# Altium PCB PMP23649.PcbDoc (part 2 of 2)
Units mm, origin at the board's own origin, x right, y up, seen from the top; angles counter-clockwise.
Board outline 75 x 70 mm, 2 copper layers (Top Layer, Bottom Layer), stack 1.575 mm thick; 49 components, 23 nets, 125 pads, 45 vias.
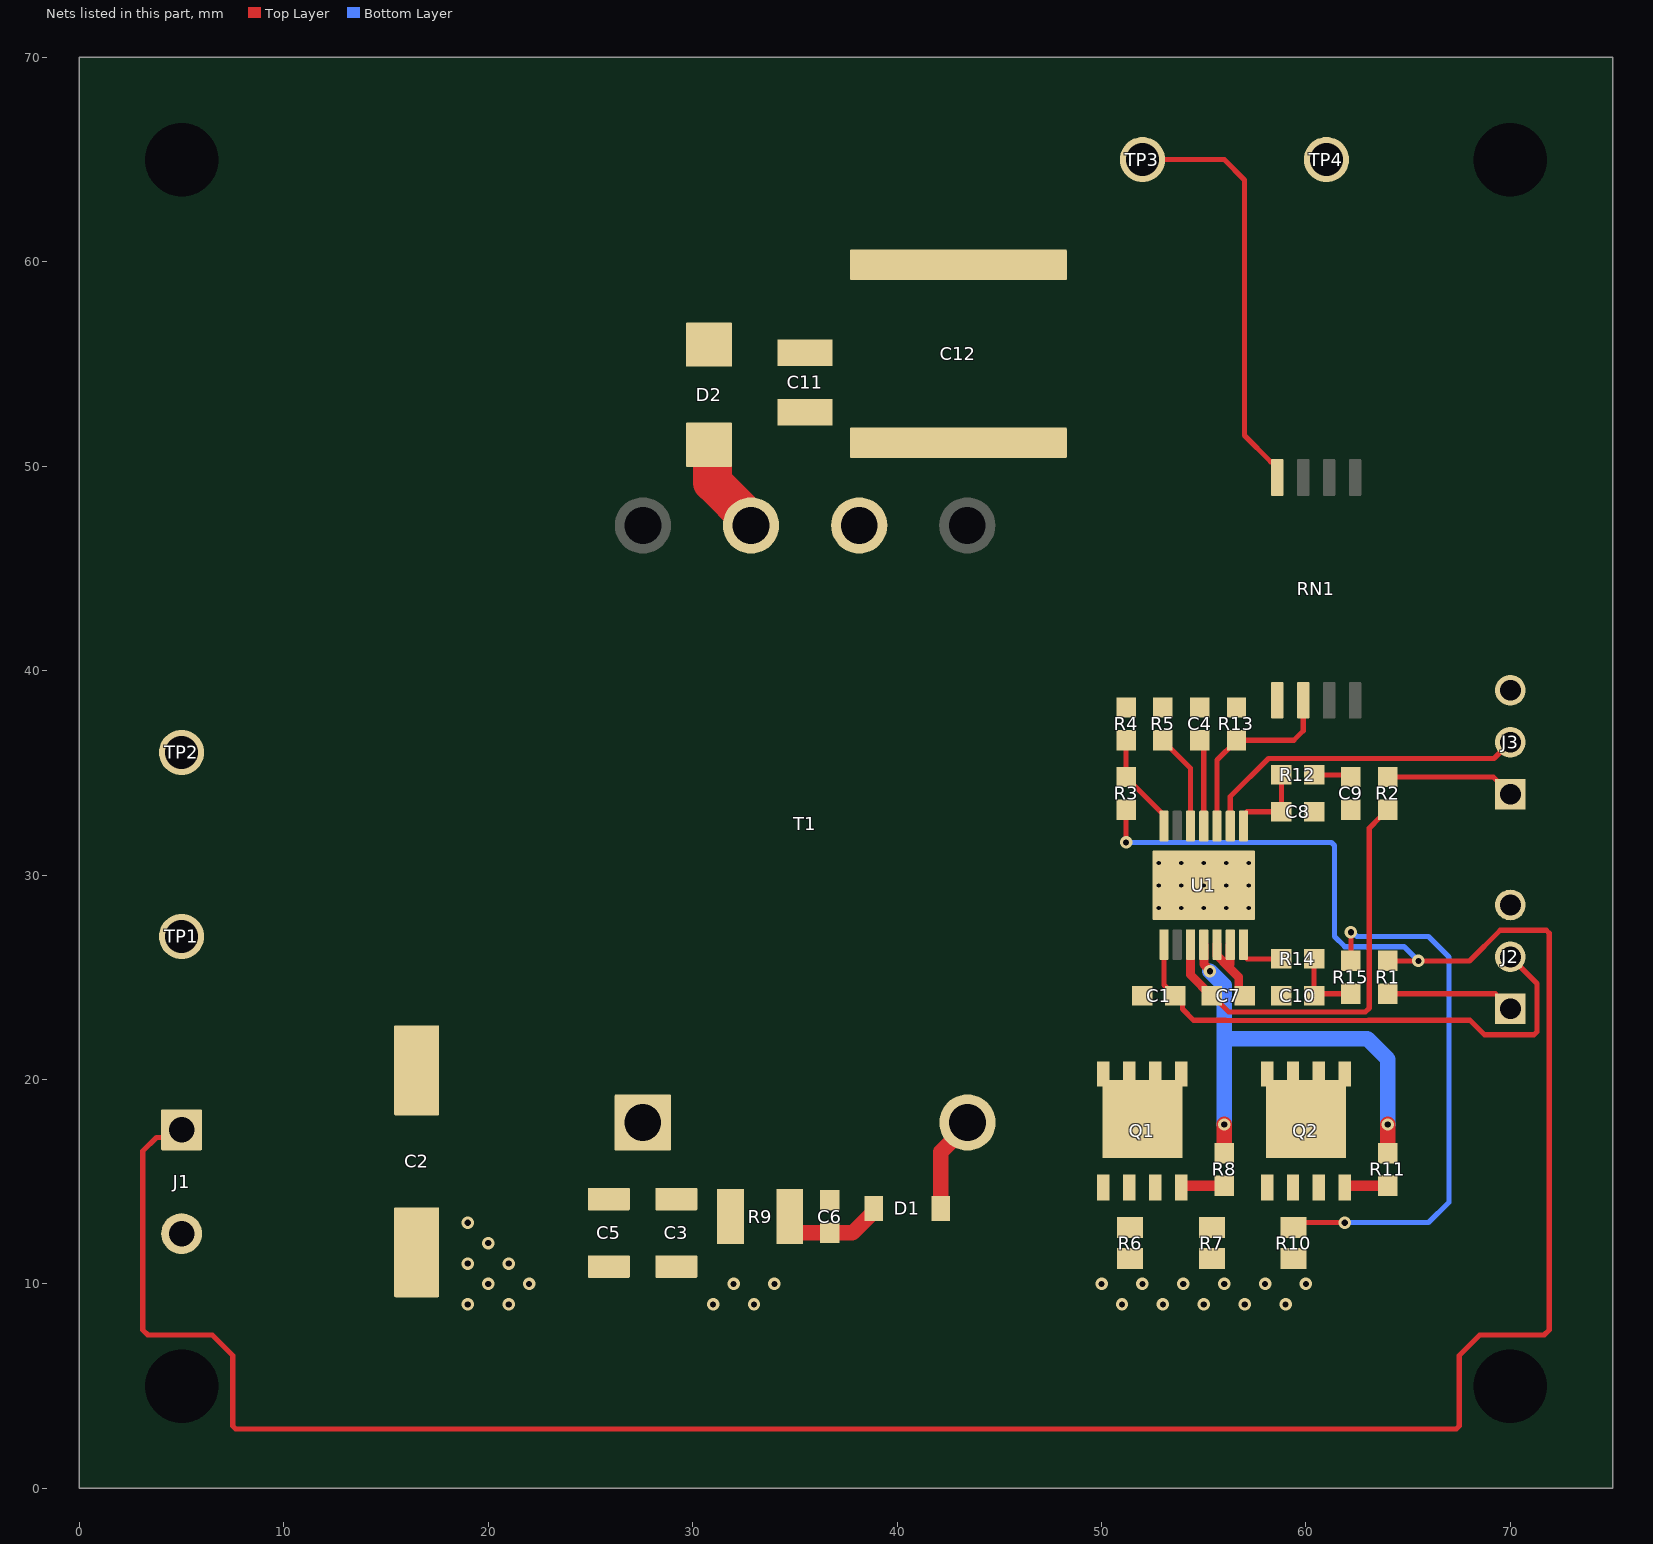
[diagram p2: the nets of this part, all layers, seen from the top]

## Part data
C1: library part CMP-0007469-4, "CAP, CERM, 0.1 uF, 100 V, +/- 10%, X7R, 0603", Cap_Case=0603, Manufacturer=MuRata, Supplier Part Number 1=490-3285-1-ND, TempCo=X7R, Tolerance_%=10%, Value1=Unknown, Value2=100V, ValueDisplayed=0.1uF
C2: library part CMP-0122594-1, "100 µF 63 V Aluminum - Polymer Capacitors Radial, Can - SMD 30mOhm 10000 Hrs @ 105°C", Digikey Part Number=565-HHXD630ARA101MJA0GCT-ND, Leakage Current=63uA, Manufacturer=Chemi-Con, Mouser Part Number=661-HHXD630ARA101MJA, Operating Temperature Range="-55°C to +105°C", Tolerance_%=20%, ValueDisplayed=100uF
C3 C5: library part CMP-0087970-1, "10µF ±10% 100V Ceramic Capacitor X7S 1210 (3225 Metric)", Manufacturer=Murata, TempCo=22%, Tolerance_%=10%, ValueDisplayed=10uF
C4 C7: library part CMP-0007338-5, "CAP, CERM, 2.2 uF, 16 V, +/- 10%, X5R, 0603", Cap_Case=0603, Manufacturer=MuRata, TempCo=X5R, Tolerance_%=10%, Value1=Unknown, Value2=16V, ValueDisplayed=2.2uF
C6: library part CMP-0007481-5, "CAP, CERM, 3900 pF, 100 V, +/- 10%, X7R, 0603", Cap_Case=0603, Manufacturer=MuRata, Supplier Part Number 1=GRM188R72A392KA01D-ND, TempCo=X7R, Tolerance_%=10%, Value1=Unknown, Value2=100V, ValueDisplayed=3900pF
C8: library part CMP-0007442-5, "CAP, CERM, 220 pF, 50 V, +/- 10%, X7R, 0603", Cap_Case=0603, Manufacturer=MuRata, Supplier Part Number 1=490-1483-1-ND, TempCo=X7R, Tolerance_%=10%, Value1=Unknown, Value2=50V, ValueDisplayed=220pF
C9: library part CMP-0007444-5, "CAP, CERM, 0.022 uF, 50 V, +/- 10%, X7R, 0603", Cap_Case=0603, Manufacturer=MuRata, Supplier Part Number 1=490-1517-1-ND, TempCo=X7R, Tolerance_%=10%, Value1=Unknown, Value2=50V, ValueDisplayed=0.022uF
C10: library part CMP-0007208-4, "CAP, CERM, 33 pF, 50 V, +/- 5%, C0G/NP0, 0603", Cap_Case=0603, Manufacturer=MuRata, Supplier Part Number 1=490-1415-1-ND, TempCo=C0G/NP0, Tolerance_%=5%, Value1=Unknown, Value2=50V, ValueDisplayed=33pF
C11: library part CMP-0009087-1, "CAP, CERM, 4700 pF, 2000 V, +/- 10%, X7R, 1210", Cap_Case=1210, Manufacturer=Kemet, TempCo=X7R, Tolerance_%=10%, Value1=Unknown, Value2=2000V, ValueDisplayed=4700pF
C12: library part CMP-0124311-1, "0.06 µF ±10% 2000V (2kV) Ceramic Capacitor C0G, NP0 3640 (9110 Metric)", Digikey Part Number=399-CKC33C603KGGLCAUTOTR-ND, Manufacturer=KEMET, Operating Temperature Range="-55°C to +150°C", TempCo=30ppm/°C, Temperature Characteristic=C0G, Tolerance_%=10%, ValueDisplayed=0.06uF
D1: library part CMP-0076920-3, "Diode, Switching, 100 V, 0.15 A, SOD-123FL", Manufacturer=Vishay-Semiconductor, Value1=0.15A, Value2=1.2V
D2: library part CMP-0124313-1, "Rectifier Diode Schottky SiC 3.3KV 0.3A 2-Pin SMB", Digikey Part Number=1242-1172-1-ND, Forward Current=0.3A, Manufacturer="GeneSiC Semiconductor", Max Surge Forward Current=2A, Mouser Part Number=905-GAP3SLT33-214, Operating Temperature Range="-55°C to +175°C", Peak Reverse Current=1uA, ValueDisplayed=93pF
H1 H2 H3 H4: library part CMP-0003652-1, Manufacturer=Keystone, Supplier Part Number 1=36-4820-ND
J1: library part CMP-0074910-1, "Terminal Block, 5.08 mm, 2x1, Brass, TH", Color=Blue, Current_A=15A, Manufacturer="On-Shore Technology", Supplier Part Number 1=ED1609-ND, Voltage_V=300V
J2 J3: library part CMP-0002338-1, "Header, 100mil, 3x1, Tin, TH", Color=Black, Current_A=3A, Manufacturer="Sullins Connector Solutions", Supplier Part Number 1=S1012E-03-ND, Voltage_V=1.8kV
Logo1: library part CMP-0074837-1, "IEC 61010-1 Hot Surface Warning"
Logo2: library part CMP-0074835-1, "IEC 61010-1 High Voltage Warning"
Logo3: library part CMP-0074847-1, "FCC_disclaimer"
Logo4: library part CMP-0074769-1
Q1 Q2: library part CMP-0084047-1, "MOSFET, N-CH, 250 V, 18.4 A, PowerPAK SO-8", Alternate Manufacturer=None, Manufacturer=Vishay-Semiconductor, Value1="? ohm", Value2="32 nC"
R1 R2: library part CMP-0025703-4, "RES, 10, 5%, 0.1 W, AEC-Q200 Grade 0, 0603", Manufacturer=Vishay-Dale, Power_W=100mW, Supplier Part Number 1=541-10GCT-ND, TempCo="200 ppm/C", Tolerance_%=5%, Value2=0.1W, Value_Code=10R0, ValueDisplayed=10
R3: library part CMP-0021990-4, "RES, 100 k, 1%, 0.1 W, AEC-Q200 Grade 0, 0603", Manufacturer=Vishay-Dale, Power_W=100mW, Supplier Part Number 1=541-100KHCT-ND, TempCo="100 ppm/C", Tolerance_%=1%, Value2=0.1W, Value_Code=100k
R4: library part CMP-0022131-4, "RES, 1.69 k, 1%, 0.1 W, AEC-Q200 Grade 0, 0603", Manufacturer=Vishay-Dale, Power_W=100mW, Supplier Part Number 1=541-1.69KHCT-ND, TempCo="100 ppm/C", Tolerance_%=1%, Value2=0.1W, Value_Code=1k69, ValueDisplayed=1.69k
R5: library part CMP-0022597-4, "RES, 78.7 k, 1%, 0.1 W, AEC-Q200 Grade 0, 0603", Manufacturer=Vishay-Dale, Power_W=100mW, Supplier Part Number 1=541-78.7KHCT-ND, TempCo="100 ppm/C", Tolerance_%=1%, Value2=0.1W, Value_Code=78k7, ValueDisplayed=78.7k
R6 R7 R10: library part CMP-0021987-2, "RES, 0.03, 1%, 0.5 W, 0805", Manufacturer=Vishay-Dale, Power_W=500mW, Supplier Part Number 1=WSLPB-.03CT-ND, TempCo="75 ppm/C", Tolerance_%=1%, Value2=0.5W, Value_Code=R030, ValueDisplayed=0.03
R8 R11: library part CMP-0025697-4, "RES, 0, 5%, 0.1 W, AEC-Q200 Grade 0, 0603", Manufacturer=Vishay-Dale, Power_W=100mW, Supplier Part Number 1=541-0.0GCT-ND, TempCo="200 ppm/C", Tolerance_%=5%, Value2=0.1W, Value_Code=0000, ValueDisplayed=0
R9: library part CMP-0083442-1, "RES, 10 k, 5%, 0.5 W, 1210", Manufacturer=Yageo, Power_W=500mW, TempCo="100 ppm/C", Tolerance_%=5%, Value2=0.5W, Value_Code=10k0, ValueDisplayed=10k
R12: library part CMP-0022066-4, "RES, 15.0 k, 1%, 0.1 W, AEC-Q200 Grade 0, 0603", Manufacturer=Vishay-Dale, Power_W=100mW, Supplier Part Number 1=541-15.0KHCT-ND, TempCo="100 ppm/C", Tolerance_%=1%, Value2=0.1W, Value_Code=15k0, ValueDisplayed=15.0k
R13: library part CMP-0022254-4, "RES, 27.4 k, 1%, 0.1 W, AEC-Q200 Grade 0, 0603", Manufacturer=Vishay-Dale, Power_W=100mW, Supplier Part Number 1=541-27.4KHCT-ND, TempCo="100 ppm/C", Tolerance_%=1%, Value2=0.1W, Value_Code=27k4, ValueDisplayed=27.4k
R14: library part CMP-0021991-4, "RES, 100, 1%, 0.1 W, AEC-Q200 Grade 0, 0603", Manufacturer=Vishay-Dale, Power_W=100mW, Supplier Part Number 1=541-100HCT-ND, TempCo="100 ppm/C", Tolerance_%=1%, Value2=0.1W, Value_Code=100R, ValueDisplayed=100
R15: library part CMP-0022109-5, "RES, 1.00 k, 1%, 0.1 W, AEC-Q200 Grade 0, 0603", Manufacturer=Vishay-Dale, Power_W=100mW, Supplier Part Number 1=541-1.00KHCT-ND, TempCo="100 ppm/C", Tolerance_%=1%, Value2=0.1W, Value_Code=1k00, ValueDisplayed=1.00k
RN1: library part CMP-0122658-1, "Automotive, 1700-V, Precision Resistive Divider", Manufacturer="Texas Instruments", Number Of Resistors=2, Operating Temperature Range="-55°C to +150°C", TempCo=1ppm/°C, Tolerance_%=0.05%
T1: library part CMP-0124541-1, "Flyback Transformer", Manufacturer=Coilcraft, Operating Temperature Range=to, Voltage_Isolation_Vrms=3.5kV
TP1 TP3: library part CMP-0055147-2, "Test Point, Multipurpose, Red, TH", Color=Red, Manufacturer="Keystone Electronics", Supplier Part Number 1=36-5010-ND
TP2 TP4: library part CMP-0055148-2, "Test Point, Multipurpose, Black, TH", Color=Black, Manufacturer="Keystone Electronics", Supplier Part Number 1=36-5011-ND
U1: library part CMP-0090862-1, "2.2-MHz Wide VIN 65-V Non-synchronous Boost/SEPIC/Flyback Controller with 150°C Junction Temperature", Manufacturer="Texas Instruments", Max Supply Voltage=60V, Min Supply Voltage=2.97V, Nominal Supply Current=490uA, Operating Temperature Range="-40°C to +150°C", Switching Frequency=100-2200kHz

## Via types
v1: diameter 0.61, hole 0.305, Top Layer to Bottom Layer, 30 vias
v2: diameter 0.5, hole 0.2, Top Layer to Bottom Layer, 15 vias

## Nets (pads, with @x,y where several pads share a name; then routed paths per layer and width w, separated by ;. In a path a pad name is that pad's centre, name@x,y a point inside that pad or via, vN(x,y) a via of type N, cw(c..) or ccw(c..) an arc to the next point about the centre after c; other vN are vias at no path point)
GND: C1.2 C2.1 C3.1 C4.2 C5.1 C7.2 C8.2 C9.2 C10.1 C11.2 C12.1 J1.2 J2.3 J3.3 R4.1 R5.1 R6.1 R7.1 R10.1 R13.1 RN1.5 T1.5 TP2.1 TP4.1 U1.5 U1.6 U1.15 | length 4.2
  Top Layer w0.432: U1.5@55.65,26.6 55.65,26.075 56.183,25.542 ; U1.6@56.3,26.6 56.291,26.591 56.291,25.65 56.183,25.542 ; C7.2@57,24.1 56.975,24.1 56.716,24.359 56.716,25.009 56.183,25.542
  other v1: 19,9 21,9 31,9 33,9 51,9 53,9 55,9 57,9 59,9 20,10 22,10 32,10 34,10 50,10 52,10 54,10 56,10 58,10 60,10 19,11 21,11 20,12 19,13
  other v2: 52.8,28.4 53.9,28.4 55,28.4 56.1,28.4 57.2,28.4 52.8,29.5 53.9,29.5 55,29.5 56.1,29.5 57.2,29.5 52.8,30.6 53.9,30.6 55,30.6 56.1,30.6 57.2,30.6
HV: C11.1 C12.2 D2.1 RN1.4 TP3.1 | length 20.7
  Top Layer w0.254: TP3.1@52,65 56,65 57,64 57,51.5 58.277,50.223 58.422,50.223 58.595,50.05 RN1.4@58.595,49.45
NetC1_1: C1.1 J2.2 U1.1 | length 25.7
  Top Layer w0.254: U1.1@53.05,26.6 53.05,24.625 53.575,24.1 53.607,24.1 53.955,23.752 53.955,23.45 54.505,22.9 56.05,22.9 56.059,22.892 63.066,22.892 63.075,22.9 68.02,22.9 68.73,22.19 71.151,22.19 71.3,22.339 71.3,24.7 J2.2@70,26
NetC2_2: C2.2 C3.2 C5.2 C6.1 J1.1 R1.1 R3.2 R9.2 T1.1 TP1.1 | length 136.9
  Top Layer w0.254: J1.1@5,17.54 4.628,17.168 3.768,17.168 3.1,16.5 3.1,7.749 3.349,7.5 6.5,7.5 7.5,6.5 7.5,3.049 7.649,2.9 67.351,2.9 67.5,3.049 67.5,6.5 68.5,7.5 71.651,7.5 71.9,7.749 71.9,27.151 71.751,27.3 69.5,27.3 68,25.8 R1.1@64,25.8 ; v1(51.2,31.6) R3.2@51.2,33.3
  Bottom Layer w0.254: v1(51.2,31.6) 61.251,31.6 61.4,31.451 61.4,27 61.9,26.5 64.8,26.5 v1(65.5,25.8)
NetC4_1: C4.1 U1.11 | length 4.3
  Top Layer w0.254: C4.1@54.8,36.6 55,36.4 U1.11@55,32.4
NetC6_2: C6.2 D1.1 R9.1 | length 4.4
  Top Layer w0.762: R9.1@35,12.4 35,12.481 35.019,12.5 C6.2@36.7,12.5 ; C6.2@36.8,12.5 37.815,12.5 38.863,13.547 D1.1@38.863,13.7
NetC7_1: C7.1 R2.2 U1.3 | length 21.2
  Top Layer w0.254: C7.1@55.4,24.1 55.425,24.1 56.227,23.298 62.898,23.298 63.1,23.5 63.1,32.3 63.627,32.827 63.652,32.827 64,33.175 R2.2@64,33.2
  Top Layer w0.432: U1.3@54.35,26.6 54.35,25.125 55.375,24.1 C7.1@55.4,24.1
NetC8_1: C8.1 R12.2 U1.8 | length 4.2
  Top Layer w0.254: U1.8@56.95,32.4 56.95,32.925 57.125,33.1 C8.1@58.8,33.1 R12.2@58.8,34.9
NetC9_1: C9.1 R12.1 | length 1.8
  Top Layer w0.254: R12.1@60.4,34.9 62.1,34.9 C9.1@62.2,34.8
NetC10_2: C10.2 R14.2 R15.2 | length 3.6
  Top Layer w0.254: R14.2@60.4,25.9 C10.2@60.4,24.1 60.5,24.2 R15.2@62.2,24.2
NetD1_2: D1.2 Q1.5 Q1.6 Q1.7 Q1.8 Q1.9 Q2.5 Q2.6 Q2.7 Q2.8 Q2.9 T1.3 | length 4.7
  Top Layer w0.762: D1.2@42.138,13.7 42.138,16.455 43.44,17.757 T1.3@43.44,17.895
NetD2_2: D2.2 T1.6 | length 4.8
  Top Layer w1.905: D2.2@30.8,51.05 30.85,51.05 30.977,50.922 30.977,49.211 32.855,47.334 T1.6@32.855,47.105
NetJ2_1: J2.1 R1.2 | length 6.3
  Top Layer w0.254: R1.2@64,24.2 69.26,24.2 J2.1@70,23.46
NetJ3_1: J3.1 R2.1 | length 6.3
  Top Layer w0.254: R2.1@64,34.8 69.16,34.8 J3.1@70,33.96
NetJ3_2: J3.2 U1.9 | length 16.2
  Top Layer w0.254: U1.9@56.3,32.4 56.3,33.837 58.165,35.702 63.681,35.702 63.683,35.7 69.2,35.7 J3.2@70,36.5
NetQ1_1: Q1.1 Q1.2 Q1.3 Q2.1 Q2.2 Q2.3 R6.2 R7.2 R10.2 R15.1 | length 26.6
  Top Layer w0.254: R10.2@59.6,12.8 59.8,13 v1(61.9,13) ; R15.1@62.2,25.8 v1(62.2,27.2)
  Bottom Layer w0.254: v1(61.9,13) 66,13 67,14 67,26 66,27 62.496,27 62.296,27.2 v1(62.2,27.2)
NetQ1_4: Q1.4 R8.1 | length 2.2
  Top Layer w0.508: Q1.4@53.9,14.7 53.9,14.744 53.956,14.8 R8.1@56,14.8
NetQ2_4: Q2.4 R11.1 | length 2
  Top Layer w0.508: Q2.4@62,14.8 R11.1@64,14.8
NetR3_1: R3.1 R4.2 U1.14 | length 5
  Top Layer w0.254: R4.2@51.2,36.6 R3.1@51.2,34.8 51.548,34.452 51.548,34.427 53.05,32.925 U1.14@53.05,32.4
NetR5_2: R5.2 U1.12 | length 4.8
  Top Layer w0.254: R5.2@53,36.6 53,36.575 54.35,35.225 U1.12@54.35,32.4
NetR8_2: R8.2 R11.2 U1.4 | length 23.6
  Top Layer w0.432: U1.4@55,26.6 55.009,26.591 55.009,25.639 55.3,25.348 v1(55.3,25.3)
  Top Layer w0.762: R8.2@56,16.4 v1(56,17.8) ; R11.2@64,16.4 v1(64,17.8)
  Bottom Layer w0.762: v1(55.3,25.3) 56,24.6 56,22 ; v1(56,17.8) 56,22 ; v1(64,17.8) 64,21 63,22 56,22
NetR13_2: R13.2 RN1.6 U1.10 | length 9.5
  Top Layer w0.254: U1.10@55.65,32.4 55.65,35.625 56.6,36.575 R13.2@56.6,36.6 59.4,36.6 59.865,37.065 RN1.6@59.865,38.55
NetR14_1: R14.1 U1.7 | length 2.4
  Top Layer w0.254: U1.7@56.95,26.6 56.95,26.075 57.125,25.9 R14.1@58.8,25.9
pads on no net: H1.0 H1.MH H2.0 H2.MH H3.0 H3.MH H4.0 H4.MH RN1.1 RN1.2 RN1.3 RN1.7 RN1.8 T1.4 T1.7 U1.2 U1.13

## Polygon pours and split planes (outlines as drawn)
GND on Top Layer "TOP_LAYER_GND_P004" (solid, remove dead copper, pour order 4): 34,53.5 34,51.8 34.2,51.8 36.5,49.5 36.5,46 37,45.5 39.5,45.5 40,46 40,47.8 41.2,49 47,49 48.5,47.5 48.5,15.8 3.1,15.8 3,15.7 3,2.4 72,2.4 72,41 57,41 55,43 55,48.5 51.5,52 38.5,52 37,53.5
NetC2_2 on Top Layer "TOP_LAYER_NETC2_2_P003" (solid, remove dead copper, pour order 3): 3,16 3,30 22.5,30 22.5,22.5 25,20 38,20 38,12 23,12 19,16
NetQ1_1 on Top Layer "TOP_LAYER_NETQ1_1_P002" (solid, remove dead copper, pour order 2): 49.6,16 49.6,12.3 61.1,12.3 61.1,16
NetD1_2 on Top Layer "TOP_LAYER_NETD1_2_P001" (solid, remove dead copper, pour order 1): 62.6,16 41.5,16 41.5,19.5 43.2,21.2 62.4,21.2 62.6,21
HV on Top Layer "TOP_LAYER_HV_P000" (solid, remove dead copper, pour order 0): 25,54.7 54,54.7 54,67 25,67
GND on Bottom Layer "BOTTOM_LAYER_GND_P005" (solid, remove dead copper, pour order 5): 7.4,6.4 6.4,7.4 3,7.4 3,39 22.5,39 22.5,15.7 48.5,15.7 48.5,47.5 47,49 41.2,49 40,47.8 40,46 39.5,45.5 37,45.5 36.5,46 36.5,53 38.5,55 49,55 57,63 57,67 67.6,67 67.6,64 69,62.6 72,62.6 72,7.4 68.6,7.4 67.6,6.4 67.6,3 7.4,3

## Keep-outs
Keep-Out Layer:
  text ".Layer_Name" at 14.656,-21.806 h1.52

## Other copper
Top Layer:
  rectangle net GND: 55.442,25.9 56.5,28
  text ".Layer_Name" at 14.656,-21.806 h1.52
Bottom Layer:
  text ".Layer_Name" at 14.656,-21.806 h1.52

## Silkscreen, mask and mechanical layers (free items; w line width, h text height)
Top Overlay:
  text "'.PRJ_Number'.PCB_Rev" at 11,5.8 h2.75
  text ".Layer_Name" at 14.656,-21.806 h1.52
Bottom Overlay:
  text ".Layer_Name" at 14.656,-21.806 h1.52
Top Paste:
  text ".Layer_Name" at 14.656,-21.806 h1.52
Bottom Paste:
  text ".Layer_Name" at 14.656,-21.806 h1.52
Top Solder:
  text ".Layer_Name" at 14.656,-21.806 h1.52
  text ".Layer_Name" at 14.656,-21.806 h1.52
Bottom Solder:
  text ".Layer_Name" at 14.656,-21.806 h1.52
Drill Guide:
  text ".Layer_Name" at 14.656,-21.806 h1.52
M1 Board Outline:
  the board outline again, w0.254
  text ".Layer_Name" at 14.656,-21.806 h1.52
M2 Board Dimensions:
  rectangle: 0,-6.985 3.175,-3.81
  rectangle: 3.175,-10.16 12.7,-6.985
  lines w0.178: 0,-6.985 25.4,-6.985 ; 3.175,-10.16 3.175,-3.81 ; 6.35,-10.16 6.35,-3.81 ; 12.7,-10.16 12.7,-3.81 ; 19.05,-10.16 19.05,-3.81 ; 0,-10.16 25.4,-10.16 25.4,-3.81 0,-3.81 0,-10.16
  text ".Layer_Name" at 14.656,-21.806 h1.52
M3 3D STEP Top:
  text ".Layer_Name" at 14.656,-21.806 h1.52
M4 3D STEP Bottom:
  text ".Layer_Name" at 14.656,-21.806 h1.52
M5 Assembly Top:
  lines w0.254: -7.417,-23.626 160.223,-23.626 ; -7.417,-18.462 160.274,-18.462 ; -7.417,-13.297 -7.417,-28.791 94.31,-28.791 160.274,-28.791 160.274,-13.297 -7.404,-13.297 -7.404,-28.791 32.614,-28.791 ; 55.194,-28.791 55.194,-13.297 ; 87.376,-18.462 87.376,-13.297 ; 108.712,-18.462 108.712,-13.297 ; 124.511,-28.956 124.511,-23.804
  text "COMPONENTS MARKED 'DNP' SHOULD NOT BE POPULATED." at 29.299,-8.09 h1.52
  text "ASSEMBLY VARIANT:" at 29.286,-11.024 h1.52
  text ".VariantName" at 55.601,-11.024 h1.52
  text "PCB VIEWED FROM TOP SIDE" at -5.804,-16.654 h1.52
  text "BOARD #:" at 57.099,-16.654 h1.52
  text ".PRJ_Number" at 70.955,-16.654 h1.52
  text "REV:" at 92.405,-16.654 h1.52
  text ".PCB_Rev" at 99.809,-16.654 h1.52
  text "SVN REV:" at 113.69,-16.654 h1.52
  text ".VersionControl_RevNumber" at 126.543,-16.654 h1.52
  text "TID #:" at 57.099,-21.819 h1.52
  text ".TID" at 70.955,-21.819 h1.52
  text "PLOT NAME =" at -5.804,-27.034 h1.52
  text ".plot_File_Name" at 14.656,-27.034 h1.52
  text "GENERATED    :" at 57.15,-27.034 h1.52
  text ".Print_Date" at 79.235,-27.034 h1.52
  text ".Print_Time" at 97.752,-27.034 h1.52
  text "TEXAS INSTRUMENTS" at 129.87,-27.034 h1.52
M6 Assembly Bottom:
  lines w0.254: -7.429,-18.474 160.261,-18.474 ; -7.379,-23.639 160.261,-23.639 ; 28.334,-28.969 28.334,-23.817 ; 44.133,-18.474 44.133,-13.31 ; 65.468,-18.474 65.468,-13.31 ; 97.65,-28.804 97.65,-13.31 ; 120.231,-28.804 160.249,-28.804 160.249,-13.31 -7.429,-13.31 -7.429,-28.804 58.534,-28.804 160.261,-28.804 160.261,-13.31
  text "COMPONENTS MARKED 'DNP' SHOULD NOT BE POPULATED." at 154.991,-8.077 h1.52
  text ".VariantName" at 128.473,-11.024 h1.52
  text "ASSEMBLY VARIANT:" at 154.864,-11.024 h1.52
  text ".VersionControl_RevNumber" at 26.302,-16.667 h1.52
  text "SVN REV:" at 39.154,-16.667 h1.52
  text ".PCB_Rev" at 53.035,-16.667 h1.52
  text "REV:" at 60.439,-16.667 h1.52
  text ".PRJ_Number" at 81.89,-16.667 h1.52
  text "BOARD #:" at 95.745,-16.667 h1.52
  text "PCB VIEWED FROM BOTTOM SIDE" at 158.648,-16.667 h1.52
  text ".TID" at 81.89,-21.831 h1.52
  text "TID #:" at 95.745,-21.831 h1.52
  text "TEXAS INSTRUMENTS" at 22.974,-27.047 h1.52
  text ".Print_Time" at 55.093,-27.047 h1.52
  text ".Print_Date" at 73.609,-27.047 h1.52
  text "GENERATED    :" at 95.694,-27.047 h1.52
  text ".plot_File_Name" at 138.189,-27.047 h1.52
  text "PLOT NAME =" at 158.648,-27.047 h1.52
M9 Title Sheet:
  drawing of 57 lines, arcs and shapes, not listed
  text "1" at 18.792,204.127 h1.78
  text "2" at 82.182,204.127 h1.78
  text "3" at 145.411,204.127 h1.78
  text "4" at 209.08,204.127 h1.78
  text "5" at 272.555,204.127 h1.78
  text "6" at 336.182,204.127 h1.78
  text "A" at -10.579,175.095 h1.78
  text "A" at 365.341,175.095 h1.78
  text "B" at -10.579,114.643 h1.78
  text "B" at 365.341,114.643 h1.78
  text "C" at -10.579,54.318 h1.78
  text "C" at 365.341,54.318 h1.78
  text "PROJECT TITLE:" at 288.125,7.048 h1.14
  text ".PRJ_Title" at 289.395,3.662 h1.78
  text "DESIGNED FOR:" at 288.125,-0.597 h1.14
  text ".PRJ_Customer" at 289.395,-4.153 h1.78
  text "D" at -10.579,-5.88 h1.78
  text "D" at 365.341,-5.88 h1.78
  text "FILE NAME:" at 288.125,-8.217 h1.14
  text ".PCB_File_Name_No_Path" at 289.395,-11.265 h1.78
  text "Texas Instruments (TI) and/or its licensors do not warrant the accuracy or completeness of this specification" at 161.9,-15.376 h1.14
  text "ENGINEER:" at 288.125,-15.583 h1.14
  text "LAYOUT BY:" at 326.352,-15.583 h1.14
  text "or any information contained therein. TI and/or its licensors do not warrant that this design will meet" at 160.757,-18.237 h1.14
  text ".PRJ_Engineer" at 289.395,-19.52 h1.78
  text ".PCB_Layout" at 327.635,-19.52 h1.78
  text "the specifications, will be suitable for your application or fit for any particular purpose, or will operate in" at 160.757,-21.099 h1.14
  text ".Layer_Name" at 14.656,-21.806 h1.52
  text "ALTIUM DESIGNER VERSION:" at 326.352,-23.457 h1.14
  text "an implementation. TI and/or its licensors do not warrant that the design is production worthy. You should" at 160.757,-23.961 h1.14
  text "completely validate and test your design implementation to confirm the system functionality for your application." at 161.9,-26.822 h1.14
  text ".print_Scale" at 289.395,-26.843 h1.78
  text ".Application_BuildNumber" at 327.635,-26.843 h1.78
  text "1" at 18.792,-32.093 h1.78
  text "2" at 82.182,-32.093 h1.78
  text "3" at 145.411,-32.093 h1.78
  text "4" at 209.08,-32.093 h1.78
  text "5" at 272.555,-32.093 h1.78
  text "6" at 336.182,-32.093 h1.78
M10 Fab Notes:
  drawing of 189 lines, arcs and shapes, not listed
  text "DESIGN INFORMATION" at 314.503,161.447 h1.52
  text "MIN. TRACK WIDTH:" at 298.131,158.091 h1.52
  text "8" at 325.976,158.091 h1.52
  text "MIL" at 329.907,158.091 h1.52
  text "7.874" at 321.75,155 h1.52
  text "MIN. CLEARANCE:" at 298.131,154.938 h1.52
  text "MIL" at 329.907,154.938 h1.52
  text "MIN. VIA PAD SIZE:" at 298.131,151.785 h1.52
  text "24" at 325.214,151.785 h1.52
  text "MIL" at 329.907,151.785 h1.52
  text "0.05mm (2MIL)" at 315.784,148.486 h1.52
  text "MINIMUM ANNULAR RING" at 289.769,148.277 h1.52
  text "EXTERNAL" at 333.768,148.277 h1.52
  text "PER" at 294.849,145.48 h1.52
  text "IPC-D-275 CLASS 2 LEVEL C" at 300.437,145.48 h1.52
  text "MIL, HOLES" at 338.238,142.928 h1.52
  text "+/-" at 328.27,142.709 h1.52
  text "+/-" at 349.961,142.709 h1.52
  text "REGISTRATION TOLERANCES:" at 289.769,142.682 h1.52
  text "METAL" at 320.243,142.682 h1.52
  text "5" at 334.879,142.683 h1.52
  text "3" at 356.037,142.683 h1.52
  text "MIL" at 358.99,142.682 h1.52
  text "HOLE SIZE TOLERANCE (UNLESS OTHERWISE SPECIFIED):" at 289.769,140.185 h1.52
  text "+/-" at 349.961,140.112 h1.52
  text "3" at 356.037,140.085 h1.52
  text "MIL" at 358.99,140.085 h1.52
  text "MATERIAL:" at 287.87,136.589 h1.52
  text "FR-4 High Tg" at 312.926,133.324 h1.52
  text "X" at 309.257,133.122 h1.52
  text "FR-4" at 298.563,133.007 h1.52
  text "OTHER" at 336.358,133.007 h1.52
  text "62 MIL (1.6mm) +/-10%" at 306.694,129.374 h1.52
  text "X" at 303.643,129.312 h1.52
  text "THICKNESS:" at 289.769,129.165 h1.52
  text "OTHER" at 339.33,129.165 h1.52
  text "TOLERANCE:" at 289.769,125.652 h1.52
  text "X" at 311.314,125.652 h1.52
  text "ANSI IPC-6012 TYPE 3 CLASS 2" at 315.836,125.652 h1.52
  text "OTHER +/-" at 315.835,121.989 h1.52
  text "BOW & TWIST:" at 289.769,118.302 h1.52
  text "X" at 311.314,118.302 h1.52
  text "ANSI IPC-6012 TYPE 3 CLASS 2" at 315.836,118.302 h1.52
  text "OTHER +/-" at 315.835,114.576 h1.52
  text "DRILLING:" at 287.87,111.258 h1.52
  text "NC_DRILL FILES" at 332.599,108.586 h1.52
  text "REFERENCE:" at 289.769,108.486 h1.52
  text "X" at 306.463,108.484 h1.52
  text "AS SHOWN" at 310.984,108.486 h1.52
  text "X" at 329.348,108.486 h1.52
  text "OTHER" at 340.168,104.873 h1.52
  text "PTH COPPER THICKNESS:" at 289.761,104.783 h1.52
  text "X" at 318.697,104.783 h1.52
  text "20-30 um" at 321.948,104.783 h1.52
  text "BOARD FINISH:" at 287.87,101.034 h1.52
  text "SILKSCREEN:" at 291.812,98.237 h1.52
  text "X" at 316.14,98.237 h1.52
  text "TOP" at 319.112,98.237 h1.52
  text "X" at 329.094,98.237 h1.52
  text "BOTTOM" at 332.091,98.237 h1.52
  text "SILKSCREEN COLOR:" at 291.812,94.295 h1.52
  text "X" at 316.115,94.295 h1.52
  text "WHITE" at 319.112,94.295 h1.52
  text "OTHER" at 332.091,94.295 h1.52
  text "X" at 319.442,90.652 h1.52
  text "GREEN" at 322.439,90.652 h1.52
  text "OTHER" at 338.136,90.652 h1.52
  text "SOLDER RESIST COLOR:" at 291.812,90.477 h1.52
  text "X" at 319.442,86.734 h1.52
  text "MATTE" at 322.439,86.734 h1.52
  text "SEMI-GLOSS" at 338.125,86.717 h1.52
  text "IMMERSION GOLD (ENIG)" at 314.819,82.345 h1.52
  text "ENEPIG" at 348.793,82.162 h1.52
  text "SURFACE FINISH:" at 287.87,82.136 h1.52
  text "X" at 310.298,82.136 h1.52
  text "IMM. TIN/SILVER OR EQUIV" at 296.24,78.649 h1.52
  text "OTHER" at 332.599,78.549 h1.52
  text "ARRAY/PANEL:" at 287.87,74.602 h1.52
  text "CUT AND TRIM PER M1 BOARD OUTLINE" at 314.819,74.393 h1.52
  text "N.C. ROUTE" at 314.819,70.94 h1.52
  text "X" at 332.295,70.94 h1.52
  text "V. SCORE" at 336.816,70.94 h1.52
  text "CERTIFICATION:" at 287.87,67.66 h1.52
  text "MATERIALS AND WORKMANSHIP FOR ALL PCBS" at 306.285,67.66 h1.52
  text "TO MEET OR EXCEED THE REQUIREMENTS OF:" at 306.285,65.271 h1.52
  text "X" at 297.078,62.003 h1.52
  text "ANSI IPC-A-600F CLASS ->" at 300.329,62.003 h1.52
  text "X" at 342.188,62.003 h1.52
  text "2" at 344.982,62.003 h1.52
  text "1" at 336.981,61.965 h1.52
  text "3" at 353.973,61.965 h1.52
  text "X" at 317.702,58.252 h1.52
  text "RoHS" at 320.953,58.252 h1.52
  text "OTHER" at 337.321,58.252 h1.52
  text "PER ORDER" at 347.407,58.252 h1.52
  text "ALL BOARDS MUST MEET OR EXCEED UL94-V0 REQUIREMENTS." at 288.569,54.345 h1.52
  text "PCB MUST BEAR THE UL94V-0 UL REGISTERED MATERIAL ID NUMBER" at 288.569,51.397 h1.52
  text "ADDITIONAL REQUIREMENTS:" at 287.87,47.094 h1.52
  text "MICROSECTION:" at 289.769,44.373 h1.52
  text "YES" at 312.775,44.373 h1.52
  text "REQUIRED" at 334.657,40.707 h1.52
  text "BARE BOARD ELEC. TEST:" at 289.769,40.634 h1.52
  text "NONE" at 322.935,40.634 h1.52
  text "X" at 331.66,40.634 h1.52
  text "PER ORDER" at 349.693,40.634 h1.52
  text "XX MIL VIAS REQUIRE NON-CONDUCTIVE FILL AND PLANARIZE" at 294.04,35.428 h1.5
  text "XX MIL VIAS REQUIRE CONDUCTIVE FILL AND PLANARIZE" at 294.243,32.787 h1.52
  text "OUTER XX MIL TRACES REQUIRE 50 OHM SINGLE-ENDED IMPEDANCE" at 294.218,28.637 h1.47
  text "LAYER 2 & 3 (INNER LAYERS) XX MIL WIDE, XX MIL SPACE / TRACES REQUIRE 100 OHM DIFFERENTIAL IMPEDANCE" at 294.015,22.65 h1.52
  text ".Layer_Name" at 14.656,-21.806 h1.52
M11 Gerber Information:
  lines w0.254: -7.417,-23.626 160.223,-23.626 ; -7.417,-18.462 160.274,-18.462 ; -7.417,-13.297 -7.417,-28.791 94.31,-28.791 160.274,-28.791 160.274,-13.297 -7.404,-13.297 -7.404,-28.791 32.614,-28.791 ; 55.194,-28.791 55.194,-13.297 ; 87.376,-18.462 87.376,-13.297 ; 108.712,-18.462 108.712,-13.297 ; 124.511,-28.956 124.511,-23.804
  text "ALL ARTWORK VIEWED FROM TOP SIDE" at -5.804,-16.654 h1.52
  text "BOARD #:" at 57.099,-16.654 h1.52
  text ".PRJ_Number" at 70.955,-16.654 h1.52
  text "REV:" at 92.405,-16.654 h1.52
  text ".PCB_Rev" at 99.809,-16.654 h1.52
  text "SVN REV:" at 113.69,-16.654 h1.52
  text ".VersionControl_RevNumber" at 126.543,-16.654 h1.52
  text "LAYER NAME =" at -5.804,-21.806 h1.52
  text "TID #:" at 57.099,-21.819 h1.52
  text ".TID" at 70.955,-21.819 h1.52
  text "PLOT NAME =" at -5.804,-27.034 h1.52
  text ".plot_File_Name" at 14.656,-27.034 h1.52
  text "GENERATED    :" at 57.15,-27.034 h1.52
  text ".Print_Date" at 79.235,-27.034 h1.52
  text ".Print_Time" at 97.752,-27.034 h1.52
  text "TEXAS INSTRUMENTS" at 129.87,-27.034 h1.52
M12 Stackup:
  drawing of 191 lines, arcs and shapes, not listed
  text "Layer" at 249.469,200.023 h1.52
  text "Name" at 259.88,200.023 h1.52
  text "Material" at 283.496,200.023 h1.52
  text "Thickness" at 305.334,200.023 h1.52
  text "Constant" at 321.84,200.023 h1.52
  text "Board Layer Stack" at 336.314,200.023 h1.52
  text "Top Overlay" at 259.88,196.975 h1.52
  text "Top Solder" at 259.88,193.927 h1.52
  text "Solder Resist" at 283.496,193.927 h1.52
  text "0.40mil" at 305.334,193.927 h1.52
  text "3.5" at 321.84,193.927 h1.52
  text "1" at 249.469,190.879 h1.52
  text "Top Layer" at 259.88,190.879 h1.52
  text "1.40mil" at 305.334,190.879 h1.52
  text "Dielectric1" at 259.88,187.831 h1.52
  text "FR-4 High Tg" at 283.496,187.831 h1.52
  text "59.20mil" at 305.334,187.831 h1.52
  text "4.8" at 321.84,187.831 h1.52
  text "2" at 249.469,184.783 h1.52
  text "Bottom Layer" at 259.88,184.783 h1.52
  text "1.40mil" at 305.334,184.783 h1.52
  text "Bottom Solder" at 259.88,181.735 h1.52
  text "Solder Resist" at 283.496,181.735 h1.52
  text "0.40mil" at 305.334,181.735 h1.52
  text "3.5" at 321.84,181.735 h1.52
  text "Bottom Overlay" at 259.88,178.687 h1.52
  text ".Layer_Name" at 14.656,-21.806 h1.52
M13 Component Bodies Top:
  text ".Layer_Name" at 14.656,-21.806 h1.52
M14 Component Bodies Bottom:
  text ".Layer_Name" at 14.656,-21.806 h1.52
M15 Courtyards Top:
  text ".Layer_Name" at 14.656,-21.806 h1.52
M16 Courtyards Bottom:
  text ".Layer_Name" at 14.656,-21.806 h1.52
Drill Drawing:
  text ".Layer_Name" at 14.656,-21.806 h1.52
M17 Embedded Cavity:
  text ".Layer_Name" at 14.656,-21.806 h1.52
M18 Embedded Assembly:
  text ".Layer_Name" at 14.656,-21.806 h1.52
M19 Embedded Keepout:
  text ".Layer_Name" at 14.656,-21.806 h1.52

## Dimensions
0,-10.16 to 25.4,-10.16 on M2 Board Dimensions
0,70 to 75,0 on M2 Board Dimensions
75,0 to 0,70 on M2 Board Dimensions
